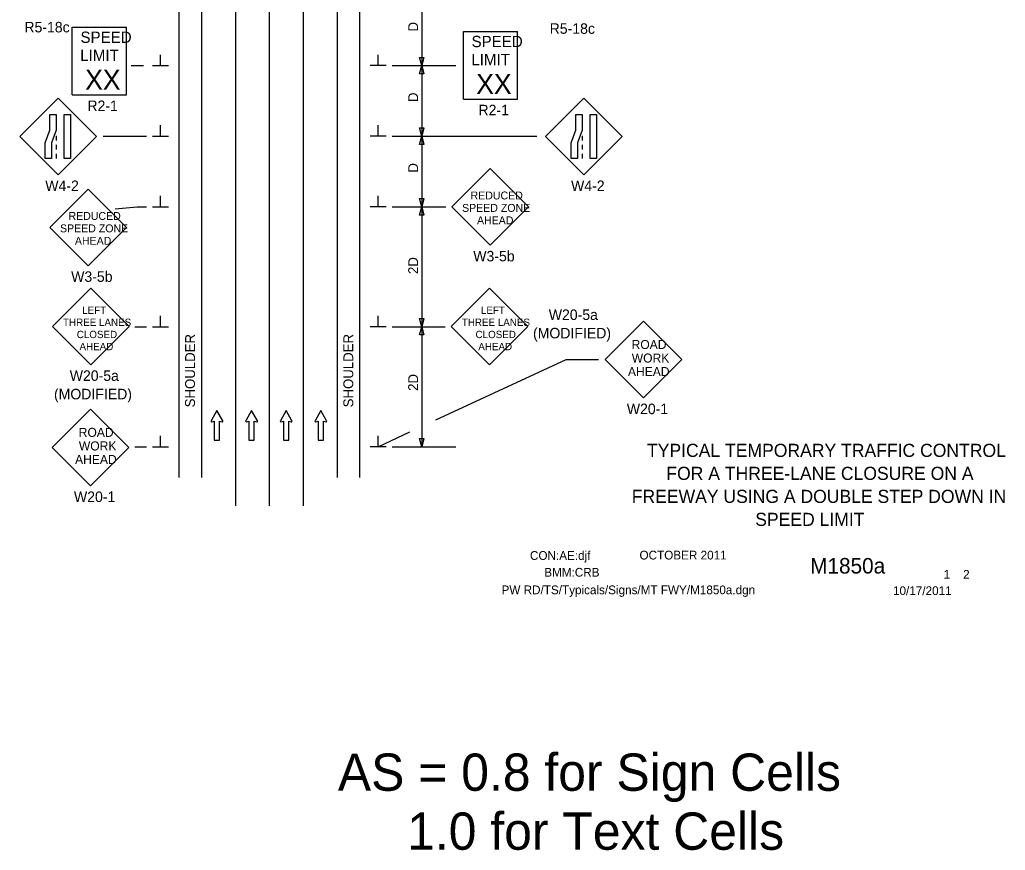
# Model space of a CAD drawing. Extents: x 16728 to 18479, y 5752 to 6927.
# Drawn here: x 16729 to 17427, y 5752 to 6341 of the extents above; entities that cross this region are included whole.
import ezdxf

# ---------------------------------------------------------------- set-up
doc = ezdxf.new("R2010")
doc.units = 0
for name, color, linetype in [('ALI_LEGAL_EX', 7, 'Continuous'), ('BORDER', 7, 'Continuous'), ('BORDER_SIGNAL_WO', 7, 'Continuous'), ('MT_SCRATCH_LEVEL_E', 7, 'Continuous'), ('PAVT_EDGE_EX', 7, 'Continuous'), ('TRAFFIC_SIGNS_PR', 7, 'Continuous'), ('TYPICAL_TEXT_DIMEN_PR', 7, 'Continuous')]:
    doc.layers.add(name, color=color, linetype=linetype)

msp = doc.modelspace()

# ---------------------------------------------------------------- linework, layer by layer
at = {"layer": 'ALI_LEGAL_EX'}
for p, q in [((16881.97, 6876.43), (16881.97, 5996.39)), ((16905.97, 6876.43), (16905.97, 5996.39)), ((16929.97, 6876.43), (16929.97, 5996.39))]:
    msp.add_line(p, q, dxfattribs=at)
for points in [[(16881.97, 6246.46), (16881.97, 6221.46)], [(16905.97, 6246.46), (16905.97, 6221.46)], [(16929.97, 6246.46), (16929.97, 6221.46)], [(16881.97, 6146.46), (16881.97, 6121.46)], [(16905.97, 6146.46), (16905.97, 6121.46)], [(16929.97, 6146.46), (16929.97, 6121.46)], [(16881.97, 6046.46), (16881.97, 6021.46)], [(16905.97, 6046.46), (16905.97, 6021.46)], [(16929.97, 6046.46), (16929.97, 6021.46)]]:
    msp.add_lwpolyline(points, dxfattribs=at)
at = {"layer": 'MT_SCRATCH_LEVEL_E'}
for p, q in [((16868.88, 6063.86), (16864.76, 6056.62)), ((16873.02, 6056.62), (16868.88, 6063.86)), ((16893.4, 6063.86), (16889.29, 6056.62)), ((16897.55, 6056.62), (16893.4, 6063.86)), ((16917.93, 6063.86), (16913.82, 6056.62)), ((16922.08, 6056.62), (16917.93, 6063.86)), ((16942.49, 6063.86), (16938.38, 6056.62)), ((16946.64, 6056.62), (16942.49, 6063.86)), ((16865.25, 6055.94), (16867.02, 6056.25)), ((16867.02, 6056.25), (16867.02, 6042.99)), ((16870.77, 6042.99), (16870.77, 6056.25)), ((16870.77, 6056.25), (16872.54, 6055.94)), ((16889.78, 6055.94), (16891.55, 6056.25)), ((16891.55, 6056.25), (16891.55, 6042.99)), ((16895.3, 6042.99), (16895.3, 6056.25)), ((16895.3, 6056.25), (16897.07, 6055.94)), ((16914.31, 6055.94), (16916.08, 6056.25)), ((16916.08, 6056.25), (16916.08, 6042.99)), ((16919.82, 6042.99), (16919.82, 6056.25)), ((16919.82, 6056.25), (16921.6, 6055.94)), ((16938.86, 6055.94), (16940.64, 6056.25)), ((16940.64, 6056.25), (16940.64, 6042.99)), ((16944.38, 6042.99), (16944.38, 6056.25)), ((16944.38, 6056.25), (16946.16, 6055.94)), ((16867.02, 6042.99), (16870.77, 6042.99)), ((16891.55, 6042.99), (16895.3, 6042.99)), ((16916.08, 6042.99), (16919.82, 6042.99)), ((16940.64, 6042.99), (16944.38, 6042.99))]:
    msp.add_line(p, q, dxfattribs=at)
for centre, start, end in [((16865.17, 6056.39), 150.42484, 279.96381), ((16872.61, 6056.39), 260.03619, 29.77312), ((16889.7, 6056.39), 150.42484, 279.96381), ((16897.14, 6056.39), 260.03619, 29.77312), ((16914.23, 6056.39), 150.42484, 279.96381), ((16921.67, 6056.39), 260.03619, 29.77312), ((16938.79, 6056.39), 150.42484, 279.96381), ((16946.23, 6056.39), 260.03619, 29.77312)]:
    msp.add_arc(centre, 0.463, start, end, dxfattribs=at)
at = {"layer": 'PAVT_EDGE_EX'}
for p, q in [((16841.97, 6926.69), (16841.97, 6016.42)), ((16857.97, 6926.69), (16857.97, 6016.42)), ((16953.97, 6926.69), (16953.97, 6016.42)), ((16969.97, 6926.69), (16969.97, 6016.42))]:
    msp.add_line(p, q, dxfattribs=at)
at = {"layer": 'TRAFFIC_SIGNS_PR'}
for p, q in [((16766.44, 6335.57), (16804.84, 6335.57)), ((16766.44, 6287.57), (16766.44, 6335.57)), ((16804.84, 6287.57), (16804.84, 6335.57)), ((17043.52, 6332.56), (17081.92, 6332.56)), ((17043.52, 6284.56), (17043.52, 6332.56)), ((17081.92, 6284.56), (17081.92, 6332.56)), ((16756.31, 6285.2), (16729.16, 6258.05)), ((16783.46, 6258.05), (16756.31, 6285.2)), ((16766.44, 6287.57), (16804.84, 6287.57)), ((17128.85, 6285.2), (17101.69, 6258.05)), ((17156, 6258.05), (17128.85, 6285.2)), ((17043.52, 6284.56), (17081.92, 6284.56)), ((16729.16, 6258.05), (16756.31, 6230.89)), ((16755.06, 6258.54), (16755.06, 6255.34)), ((16756.31, 6230.89), (16783.46, 6258.05)), ((17101.69, 6258.05), (17128.85, 6230.89)), ((17127.6, 6258.54), (17127.6, 6255.34)), ((17128.85, 6230.89), (17156, 6258.05)), ((16755.06, 6252.14), (16755.06, 6248.94)), ((17127.6, 6252.14), (17127.6, 6248.94)), ((16755.06, 6245.74), (16755.06, 6242.54)), ((17127.6, 6245.74), (17127.6, 6242.54)), ((17062.54, 6235.35), (17035.39, 6208.2)), ((17089.69, 6208.2), (17062.54, 6235.35)), ((16777.67, 6220.84), (16750.51, 6193.68)), ((16804.82, 6193.68), (16777.67, 6220.84)), ((17035.39, 6208.2), (17062.54, 6181.04)), ((17062.54, 6181.04), (17089.69, 6208.2)), ((16750.51, 6193.68), (16777.67, 6166.53)), ((16777.67, 6166.53), (16804.82, 6193.68)), ((16779.46, 6150.64), (16752.3, 6123.49)), ((16806.61, 6123.49), (16779.46, 6150.64)), ((17062, 6150.64), (17034.85, 6123.49)), ((17089.16, 6123.49), (17062, 6150.64)), ((17171.14, 6127.12), (17143.99, 6099.96)), ((17198.29, 6099.96), (17171.14, 6127.12)), ((16752.3, 6123.49), (16779.46, 6096.33)), ((16779.46, 6096.33), (16806.61, 6123.49)), ((17034.85, 6123.49), (17062, 6096.33)), ((17062, 6096.33), (17089.16, 6123.49)), ((17143.99, 6099.96), (17171.14, 6072.81)), ((17171.14, 6072.81), (17198.29, 6099.96)), ((16779.42, 6064.84), (16752.27, 6037.69)), ((16806.57, 6037.69), (16779.42, 6064.84)), ((16752.27, 6037.69), (16779.42, 6010.53)), ((16779.42, 6010.53), (16806.57, 6037.69))]:
    msp.add_line(p, q, dxfattribs=at)
for points in [[(16755.06, 6273.78), (16755.06, 6262.6), (16751.72, 6253.72), (16751.72, 6242.54), (16747.23, 6242.54), (16747.23, 6253.72), (16750.57, 6262.6), (16750.57, 6273.78)], [(16765.2, 6273.78), (16765.2, 6242.54), (16760.71, 6242.54), (16760.71, 6273.78)], [(17127.6, 6273.78), (17127.6, 6262.6), (17124.25, 6253.72), (17124.25, 6242.54), (17119.76, 6242.54), (17119.76, 6253.72), (17123.11, 6262.6), (17123.11, 6273.78)], [(17137.73, 6273.78), (17137.73, 6242.54), (17133.24, 6242.54), (17133.24, 6273.78)]]:
    msp.add_lwpolyline(points, close=True, dxfattribs=at)
at = {"layer": 'TYPICAL_TEXT_DIMEN_PR'}
for p, q in [((17013.97, 6358.29), (17013.97, 6308.29)), ((16828.84, 6308.29), (16828.84, 6316.08)), ((16983.09, 6308.29), (16983.09, 6316.08)), ((17013.97, 6308.29), (17012.4, 6314.15)), ((17012.4, 6314.15), (17013.97, 6314.15)), ((17013.97, 6314.15), (17015.54, 6314.15)), ((17015.54, 6314.15), (17013.97, 6308.29)), ((16808.04, 6308.29), (16816.94, 6308.29)), ((16823.22, 6308.29), (16834.47, 6308.29)), ((16988.72, 6308.29), (16977.47, 6308.29)), ((16992.97, 6308.29), (17038.11, 6308.29)), ((17012.4, 6302.43), (17013.97, 6308.29)), ((17013.97, 6308.29), (17015.54, 6302.43)), ((17013.97, 6308.29), (17013.97, 6258.29)), ((17013.97, 6302.43), (17012.4, 6302.43)), ((17015.54, 6302.43), (17013.97, 6302.43)), ((16828.84, 6258.29), (16828.84, 6266.08)), ((16983.09, 6258.29), (16983.09, 6266.08)), ((17013.97, 6258.29), (17012.4, 6264.15)), ((17012.4, 6264.15), (17013.97, 6264.15)), ((17013.97, 6264.15), (17015.54, 6264.15)), ((17015.54, 6264.15), (17013.97, 6258.29)), ((16788.28, 6258.29), (16818.97, 6258.29)), ((16823.22, 6258.29), (16834.47, 6258.29)), ((16988.72, 6258.29), (16977.47, 6258.29)), ((16992.97, 6258.29), (17095.5, 6258.29)), ((17012.4, 6252.43), (17013.97, 6258.29)), ((17013.97, 6258.29), (17013.97, 6208.29)), ((17013.97, 6258.29), (17015.54, 6252.43)), ((17013.97, 6252.43), (17012.4, 6252.43)), ((17015.54, 6252.43), (17013.97, 6252.43)), ((16828.84, 6208.29), (16828.84, 6216.08)), ((16983.09, 6208.29), (16983.09, 6216.08)), ((16796.9, 6206.85), (16812.39, 6208.29)), ((16812.39, 6208.29), (16818.97, 6208.29)), ((16823.22, 6208.29), (16834.47, 6208.29)), ((16988.72, 6208.29), (16977.47, 6208.29)), ((16992.97, 6208.29), (17031.06, 6208.29)), ((17013.97, 6208.29), (17012.4, 6214.15)), ((17012.4, 6214.15), (17013.97, 6214.15)), ((17012.4, 6202.43), (17013.97, 6208.29)), ((17013.97, 6214.15), (17015.54, 6214.15)), ((17015.54, 6214.15), (17013.97, 6208.29)), ((17013.97, 6208.29), (17013.97, 6123.29)), ((17013.97, 6208.29), (17015.54, 6202.43)), ((17013.97, 6202.43), (17012.4, 6202.43)), ((17015.54, 6202.43), (17013.97, 6202.43)), ((16828.84, 6123.29), (16828.84, 6131.08)), ((16983.09, 6123.29), (16983.09, 6131.08)), ((17013.97, 6123.29), (17012.4, 6129.15)), ((17012.4, 6129.15), (17013.97, 6129.15)), ((17013.97, 6129.15), (17015.54, 6129.15)), ((17015.54, 6129.15), (17013.97, 6123.29)), ((16810.75, 6123.15), (16818.97, 6123.15)), ((16823.22, 6123.29), (16834.47, 6123.29)), ((16988.72, 6123.29), (16977.47, 6123.29)), ((16992.97, 6123.29), (17030.49, 6123.29)), ((17012.4, 6117.43), (17013.97, 6123.29)), ((17013.97, 6117.43), (17012.4, 6117.43)), ((17013.97, 6123.29), (17013.97, 6038.29)), ((17013.97, 6123.29), (17015.54, 6117.43)), ((17015.54, 6117.43), (17013.97, 6117.43)), ((17023.98, 6057.21), (17116.43, 6100)), ((17116.43, 6100), (17139.3, 6100)), ((16983.09, 6038.29), (17005.65, 6048.73)), ((16828.84, 6038.29), (16828.84, 6046.08)), ((16983.09, 6038.29), (16983.09, 6046.08)), ((17013.97, 6038.29), (17012.4, 6044.15)), ((17012.4, 6044.15), (17013.97, 6044.15)), ((17013.97, 6044.15), (17015.54, 6044.15)), ((17015.54, 6044.15), (17013.97, 6038.29)), ((16810.75, 6038.12), (16818.97, 6038.12)), ((16823.22, 6038.29), (16834.47, 6038.29)), ((16988.72, 6038.29), (16977.47, 6038.29)), ((16992.97, 6038.29), (17038.11, 6038.29))]:
    msp.add_line(p, q, dxfattribs=at)

# ---------------------------------------------------------------- texts
at = {"layer": 'BORDER'}
for s, p in [('TYPICAL TEMPORARY TRAFFIC CONTROL', (17173.6, 6031.02)), ('FOR A THREE-LANE CLOSURE ON A', (17187.3, 6014.72)), ('FREEWAY USING A DOUBLE STEP DOWN IN ', (17162.8, 5998.42)), ('SPEED LIMIT', (17250.3, 5982.12))]:
    msp.add_text(s, height=9.3, dxfattribs=at).set_placement(p)
at = {"layer": 'BORDER_SIGNAL_WO'}
for s, height, p in [('CON:AE:djf  ', 6.2, (17090.69, 5958.06)), ('    OCTOBER 2011', 6.2, (17159.08, 5958.34)), ('    M1850a   ', 11, (17272.86, 5948.38)), ('BMM:CRB', 6.2, (17100.81, 5946.17)), (' 1    2 ', 6.2, (17381.45, 5944.7)), ('PW RD/TS/Typicals/Signs/MT FWY/M1850a.dgn      ', 6.2, (17070.55, 5933.71)), ('10/17/2011', 6.2, (17347.93, 5933.13)), ('AS = 0.8 for Sign Cells', 26.4241, (16954.57, 5794.42)), ('     1.0 for Text Cells', 26.4241, (16954.57, 5752.64))]:
    msp.add_text(s, height=height, dxfattribs=at).set_placement(p)
at = {"layer": 'TRAFFIC_SIGNS_PR'}
for s, height, p in [('R5-18c', 7.44, (16732.48, 6331.86)), ('R5-18c', 7.44, (17104.66, 6330.86)), ('SPEED', 8, (16772.21, 6324.43)), ('SPEED', 8, (17049.29, 6321.42)), ('LIMIT', 8, (16772.04, 6311.63)), ('LIMIT', 8, (17049.12, 6308.62)), ('XX', 14.031, (16775.55, 6291.33)), ('XX', 14.031, (17052.63, 6288.32)), ('R2-1', 7.44, (16777.12, 6276.13)), ('R2-1', 7.44, (17054.2, 6273.12)), ('W4-2', 7.44, (16747.27, 6219.46)), ('W4-2', 7.44, (17119.8, 6219.46)), ('REDUCED', 5.6, (17048.6, 6213.5)), ('SPEED ZONE', 5.6, (17042.59, 6204.7)), ('REDUCED', 5.6, (16763.72, 6198.99)), ('AHEAD', 5.6, (17053.15, 6195.9)), ('SPEED ZONE', 5.6, (16757.72, 6190.19)), ('AHEAD', 5.6, (16768.28, 6181.39)), ('W3-5b', 7.44, (17050.5, 6169.6)), ('W3-5b', 7.44, (16765.62, 6155.09)), ('LEFT', 5.2, (16773.4, 6132.42)), ('LEFT', 5.2, (17055.95, 6132.42)), ('W20-5a', 7.44, (17104, 6128.07)), ('THREE LANES', 5.2, (16759.85, 6123.82)), ('THREE LANES', 5.2, (17042.39, 6123.82)), ('CLOSED', 5.2, (16769.58, 6115.22)), ('CLOSED', 5.2, (17052.12, 6115.22)), ('(MODIFIED)', 7.44, (17092.85, 6115.03)), ('AHEAD', 5.2, (16771.52, 6106.62)), ('AHEAD', 5.2, (17054.07, 6106.62)), ('ROAD', 6.4, (17162.68, 6107.5)), ('WORK', 6.4, (17162.79, 6097.9)), ('W20-5a', 7.44, (16764.6, 6084.89)), ('AHEAD', 6.4, (17160.1, 6088.3)), ('(MODIFIED)', 7.44, (16753.45, 6071.85)), ('W20-1', 7.44, (17159.31, 6061.37)), ('ROAD', 6.4, (16770.96, 6045.22)), ('WORK', 6.4, (16771.07, 6035.62)), ('AHEAD', 6.4, (16768.38, 6026.02)), ('W20-1', 7.44, (16767.59, 5999.09))]:
    msp.add_text(s, height=height, dxfattribs=at).set_placement(p)
at = {"layer": 'TYPICAL_TEXT_DIMEN_PR'}
for s, p in [('D', (17011.41, 6332.51)), ('D', (17011.41, 6282.51)), ('D', (17011.41, 6232.51)), ('2D', (17011.41, 6160.64)), ('SHOULDER', (16853.34, 6066.16)), ('SHOULDER', (16965.48, 6066.16)), ('2D', (17011.41, 6077.85))]:
    msp.add_text(s, height=7, rotation=90, dxfattribs=at).set_placement(p)

doc.saveas('drawing.dxf')
